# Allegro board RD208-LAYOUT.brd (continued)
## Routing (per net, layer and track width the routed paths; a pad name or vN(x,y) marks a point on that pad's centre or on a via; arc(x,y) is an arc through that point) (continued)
N16690281: length 1.4
  TOP w0.6: R284.1 189.1,115.05 D71.A
N16690501: length 1.4
  TOP w0.6: D72.A 189.1,124.3 R286.1
N16690719: length 1.4
  TOP w0.6: D73.A 189.1,133.55 R288.1
N16776249: length 3.3
  TOP w0.2: 163.5,104.18 R292.2 R291.1
N16781117: length 1.4
  TOP w0.3: IC2.15 153.12,32.62 R295.2
N16783087: length 1
  TOP w0.3: R27.1 R24.1
N16783507: length 2.2
  TOP w0.2: IC2.4 v1(161.8,33.92)
  BOTTOM w0.3: v1(161.8,33.92) 162.68,33.92 R297.1
N159286810: length 1.1
  TOP w0.5: C12.1 R14.2
N159479370: length 1.5
  BOTTOM w0.8: R29.1 R28.2

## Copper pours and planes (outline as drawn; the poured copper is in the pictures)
5V_IN on TOP: 78.55,129 78.42,129.03 78.33,129.12 78.3,129.25 78.3,130.35 78.27,130.47 78.23,130.52 77.07,131.68 77.03,131.73 77,131.85 77,143.9 77.04,144.01 77.15,144.05 79.15,144.05 79.26,144.01 79.3,143.9 79.3,136.2 79.29,136.14 79.23,136.03 79.02,135.82 78.96,135.71 78.95,135.65 78.95,133.7 78.98,133.58 79.02,133.53 79.28,133.27 79.32,133.22 79.35,133.1 79.35,130.85 79.34,130.79 79.28,130.68 79.27,130.67 79.21,130.56 79.2,130.5 79.2,129.25 79.17,129.12 79.08,129.03 78.95,129
5V_RTN on TOP: 80.55,129 80.42,129.03 80.33,129.12 80.3,129.25 80.3,130.5 80.27,130.62 80.18,130.73 80.15,130.85 80.15,133.1 80.16,133.16 80.22,133.27 80.48,133.53 80.54,133.64 80.55,133.7 80.55,135.65 80.52,135.77 80.48,135.82 80.27,136.03 80.23,136.08 80.2,136.2 80.2,143.9 80.24,144.01 80.35,144.05 82.35,144.05 82.46,144.01 82.5,143.9 82.5,131.85 82.49,131.79 82.43,131.68 81.27,130.52 81.21,130.41 81.2,130.35 81.2,129.25 81.17,129.12 81.08,129.03 80.95,129
GND on BOTTOM (solid shape): 222.03,10.28 222.5,10.6 222.97,10.28 223.52,8.85 223.24,8.2 222.59,8.49 222.58,8.53 222.42,8.53 222.41,8.49 221.76,8.2 221.48,8.85
GND on TOP: 164.5,88.45 164.44,88.46 164.33,88.52 163.57,89.28 163.53,89.33 163.5,89.45 163.5,96.1 163.47,96.22 163.43,96.27 163.24,96.46 163.21,96.5 163.2,96.56 163.2,97.5 163.23,97.62 163.32,97.72 163.45,97.75 165,97.75 165.22,97.84 165.31,98.05 165.31,98.75 165.35,98.86 165.46,98.9 170.93,98.9 170.98,98.89 171.03,98.86 171.26,98.63 171.29,98.58 171.3,98.53 171.3,88.6 171.26,88.49 171.15,88.45
GND on TOP: 156.3,35.75 156.18,35.78 156.08,35.88 156.05,36 156.05,36.7 156.02,36.83 155.93,36.92 155.8,36.95 153.6,36.95 153.47,36.98 153.38,37.08 153.35,37.2 153.35,40 153.38,40.12 153.47,40.22 153.6,40.25 161.9,40.25 162.03,40.22 162.12,40.12 162.15,40 162.15,37.2 162.12,37.08 162.03,36.98 161.9,36.95 159.2,36.95 159.07,36.92 158.98,36.83 158.95,36.7 158.95,36 158.92,35.88 158.82,35.78 158.7,35.75
GND on TOP: 98.95,20.25 98.83,20.28 98.73,20.38 98.7,20.5 98.7,25.6 98.73,25.73 98.83,25.82 98.95,25.85 100.45,25.85 100.58,25.82 100.67,25.73 100.7,25.6 100.7,20.5 100.67,20.38 100.58,20.28 100.45,20.25
GND on TOP: 45.95,13.93 45.83,13.96 45.73,14.05 45.7,14.18 45.7,15.19 45.73,15.27 45.79,15.32 45.88,15.38 45.95,15.47 46,15.54 46.08,15.56 47.35,15.56 47.48,15.59 47.57,15.69 47.6,15.81 47.6,16.75 47.63,16.88 47.73,16.97 47.85,17 49.1,17 49.23,16.97 49.32,16.88 49.35,16.75 49.35,15.81 49.38,15.69 49.48,15.59 49.6,15.56 49.69,15.56 49.75,15.55 49.86,15.49 50.18,15.17 50.22,15.12 50.25,15 50.25,14.18 50.22,14.05 50.12,13.96 50,13.93
GND on TOP: 56.2,11.35 56.09,11.39 56.05,11.5 56.05,13.95 56.08,14.07 56.17,14.17 56.3,14.2 57.7,14.2 57.91,14.29 58,14.5 58,15 57.91,15.21 57.7,15.3 56.3,15.3 56.17,15.33 56.08,15.43 56.05,15.55 56.05,16.62 55.96,16.84 55.75,16.93 53.6,16.93 53.55,16.94 53.5,16.97 52.38,18.04 52.23,18.07 52.1,18.07 51.99,18.12 51.95,18.23 51.95,18.83 52.02,19.01 52.19,19.08 52.22,19.08 52.53,19.13 52.77,19.34 52.83,19.39 52.92,19.4 52.98,19.4 55.45,19.4 55.56,19.36 55.6,19.25 55.6,18.15 55.69,17.94 55.9,17.85 57.5,17.85 57.71,17.94 57.8,18.15 57.8,19.15 57.84,19.26 57.95,19.3 58.5,19.3 58.61,19.26 58.65,19.15 58.65,11.6 58.62,11.47 58.52,11.38 58.4,11.35
GND on TOP: 48.2,20.2 48.08,20.23 47.98,20.32 47.95,20.45 47.95,22.9 47.96,22.96 48.02,23.07 48.33,23.38 48.38,23.42 48.5,23.45 50.8,23.45 50.87,23.42 50.9,23.35 50.9,22.1 50.87,22.03 50.8,22 50.33,22 50.11,21.91 50.02,21.7 50.02,21.5 50,21.43 49.92,21.4 49.6,21.4 49.48,21.37 49.38,21.27 49.35,21.15 49.35,20.45 49.32,20.32 49.23,20.23 49.1,20.2
GND on TOP: 43.94,63.5 44,63.49 44.04,63.46 47,60.5 57.2,60.5 57.32,60.53 57.37,60.57 57.53,60.73 57.58,60.77 57.7,60.8 58.25,60.8 58.38,60.77 58.47,60.67 58.5,60.55 58.5,45.4 58.42,44.53 58.2,43.69 57.83,42.9 57.33,42.19 56.71,41.57 56,41.07 55.21,40.7 54.37,40.48 53.5,40.4 35.7,40.4 34.83,40.48 33.99,40.7 33.2,41.07 32.49,41.57 31.87,42.19 31.37,42.9 31,43.69 30.78,44.53 30.7,45.4 30.7,52.75 30.67,52.87 30.63,52.92 28.37,55.18 28.33,55.23 28.3,55.35 28.3,62.44 28.31,62.5 28.34,62.54 29.26,63.46 29.3,63.49 29.36,63.5 ; 1 cut-out
GND on TOP: 42.25,11.1 42.36,11.06 42.4,10.95 42.4,9.1 42.49,8.89 42.7,8.8 45.6,8.8 45.81,8.89 45.9,9.1 45.9,10.3 45.94,10.41 46.05,10.45 50.33,10.45 50.4,10.44 50.51,10.38 51.29,9.6 51.42,9.51 51.57,9.48 68.53,9.48 68.58,9.47 68.62,9.45 68.71,9.39 68.74,9.36 68.76,9.33 69.28,8.71 70.05,8.48 70.7,8.48 70.83,8.45 70.92,8.36 70.95,8.23 70.95,1.15 70.91,1.04 70.8,1 10.35,1 10.24,1.04 10.2,1.15 10.2,5 8.68,8.68 5,10.2 1.15,10.2 1.04,10.24 1,10.35 1,24.25 1.03,24.38 1.12,24.47 1.25,24.5 11.95,24.5 12.01,24.49 12.12,24.43 20.38,16.17 20.49,16.11 20.55,16.1 42.6,16.1 42.73,16.07 42.82,15.97 42.83,15.94 42.84,15.9 42.84,14.4 42.8,14.28 42.71,14.18 42.59,14.15 39.35,14.15 39.23,14.12 39.13,14.03 39.1,13.9 39.1,12.5 39.16,12.33 39.37,12.16 39.4,12.08 39.4,11.65 39.56,11.26 39.95,11.1 ; 1 cut-out
GND on TOP: 219.75,139.65 219.71,139.54 219.6,139.5 197.15,139.5 197.04,139.54 197,139.65 197,142.7 187.2,142.7 187.08,142.67 187.03,142.63 186.82,142.42 186.77,142.38 186.65,142.35 185.75,142.35 185.62,142.38 185.53,142.47 185.5,142.6 185.5,148.75 185.53,148.88 185.62,148.97 185.75,149 209.99,149 210.01,149 219.6,149 219.71,148.96 219.75,148.85 ; 1 cut-out
GND on TOP: 57.95,142.5 57.83,142.53 57.73,142.62 57.7,142.75 57.7,145 57.66,145.51 57.56,146.02 57.51,146.17 57.46,146.32 57.45,146.36 57.45,148.75 57.48,148.88 57.58,148.97 57.7,149 61.75,149 61.82,148.97 61.85,148.9 61.85,147.78 61.82,147.7 61.75,147.68 61,147.68 60.79,147.59 60.7,147.38 60.7,146.62 60.79,146.41 61,146.32 61.75,146.32 61.82,146.3 61.85,146.22 61.85,145.28 61.82,145.2 61.75,145.18 61,145.18 60.79,145.09 60.7,144.88 60.7,144.12 60.79,143.91 61,143.82 61.75,143.82 61.82,143.8 61.85,143.72 61.85,142.75 61.82,142.62 61.73,142.53 61.6,142.5
GND on TOP: 154.05,29.95 153.93,29.98 153.83,30.07 153.8,30.2 153.8,31.4 153.84,31.51 153.95,31.55 155.8,31.55 155.93,31.58 156.02,31.68 156.05,31.8 156.05,32.55 156.08,32.67 156.18,32.77 156.3,32.8 158.7,32.8 158.82,32.77 158.92,32.67 158.95,32.55 158.95,31.8 158.98,31.68 159.07,31.58 159.2,31.55 161.15,31.55 161.35,31.63 161.45,31.82 161.5,31.92 161.62,31.95 161.65,31.95 162.85,31.95 162.97,31.92 163.07,31.82 163.1,31.7 163.1,30.2 163.07,30.07 162.97,29.98 162.85,29.95
GND on BOTTOM: 57.7,146.45 57.58,146.48 57.48,146.57 57.45,146.7 57.45,148.35 57.48,148.47 57.58,148.57 57.7,148.6 60.4,148.6 60.52,148.57 60.62,148.47 60.65,148.35 60.65,146.7 60.62,146.57 60.52,146.48 60.4,146.45
GND on BOTTOM: 219.75,139.65 219.71,139.54 219.6,139.5 197.15,139.5 197.04,139.54 197,139.65 197,142.35 185.75,142.35 185.62,142.38 185.53,142.47 185.5,142.6 185.5,148.75 185.53,148.88 185.62,148.97 185.75,149 209.99,149 210.01,149 219.6,149 219.71,148.96 219.75,148.85 ; 1 cut-out
GND on BOTTOM: 164.6,88.45 164.47,88.48 164.38,88.58 164.35,88.7 164.35,98.65 164.38,98.78 164.47,98.87 164.6,98.9 170.89,98.9 170.95,98.89 171.06,98.83 171.25,98.64 171.27,98.62 171.28,98.59 171.29,98.55 171.3,98.5 171.3,88.7 171.3,88.69 171.22,88.52 171.05,88.45
GND on BOTTOM: outline of 119 points within 1,1 68.15,27.1
GND on BOTTOM: 151.46,39.96 151.5,39.99 151.56,40 163.44,40 163.5,39.99 163.54,39.96 163.96,39.54 163.99,39.5 164,39.44 164,28.6 163.99,28.54 163.93,28.43 163.57,28.07 163.52,28.03 163.4,28 151.6,28 151.54,28.01 151.43,28.07 151.07,28.43 151.03,28.48 151,28.6 151,39.44 151.01,39.5 151.04,39.54 ; 1 cut-out
GND on BOTTOM: 196.15,3.45 196.08,3.48 196.05,3.55 196.05,5.7 196.08,5.77 196.15,5.8 197.55,5.8 197.62,5.77 197.65,5.7 197.65,3.55 197.62,3.48 197.55,3.45
GND on BOTTOM: 95.5,18.5 95.44,18.51 95.33,18.57 94.62,19.28 94.58,19.33 94.55,19.45 94.55,25.4 94.56,25.46 94.62,25.57 94.98,25.93 95.03,25.97 95.15,26 114.2,26 114.26,25.99 114.37,25.93 115.78,24.52 115.82,24.47 115.85,24.35 115.85,18.75 115.82,18.62 115.72,18.53 115.6,18.5
GND on CONDUCTIVE2: outline of 142 points within 1,15.5 239,149 ; 7 cut-outs
GND on CONDUCTIVE3: 220.07,140.16 219.86,139.84 219.52,139.62 219.15,139.55 198,139.55 197.61,139.63 197.29,139.84 197.07,140.18 197,140.55 197,141.35 196.93,141.72 196.71,142.06 196.39,142.27 196,142.35 185.75,142.35 185.62,142.38 185.53,142.47 185.5,142.6 185.5,148.75 185.53,148.88 185.62,148.97 185.75,149 209.99,149 210.01,149 220,149 220.11,148.96 220.15,148.85 220.15,140.55 ; 1 cut-out
GND on CONDUCTIVE4: 52.85,136.9 52.73,136.93 52.63,137.03 52.6,137.15 52.6,141.05 52.63,141.18 52.73,141.27 52.85,141.3 53.99,141.3 57.28,143.3 57.02,147.14 57,147.17 57,147.2 57,148.9 57.03,148.97 57.1,149 61.1,149 61.17,148.97 61.2,148.9 61.2,144.5 61.19,144.44 61.13,144.33 58.02,141.22 57.96,141.11 57.95,141.05 57.95,139.55 57.94,139.48 57.88,139.37 55.65,137.15 55.59,137.07 55.56,136.98 55.52,136.92 55.46,136.9
GND on CONDUCTIVE4: 219.6,139.65 219.56,139.54 219.45,139.5 197.06,139.5 197,139.51 196.96,139.54 194.15,142.35 185.75,142.35 185.62,142.38 185.53,142.47 185.5,142.6 185.5,148.75 185.53,148.88 185.62,148.97 185.75,149 209.99,149 210.01,149 219.45,149 219.56,148.96 219.6,148.85 ; 1 cut-out
GND on CONDUCTIVE4: outline of 103 points within 1,1 229.8,39.4 ; 1 cut-out
GND on CONDUCTIVE5: 219.75,139.65 219.71,139.54 219.6,139.5 197.16,139.5 197.1,139.51 197.06,139.54 194.25,142.35 185.75,142.35 185.62,142.38 185.53,142.47 185.5,142.6 185.5,148.75 185.53,148.88 185.62,148.97 185.75,149 209.99,149 210.01,149 219.6,149 219.71,148.96 219.75,148.85 ; 1 cut-out
GND_D on TOP: outline of 96 points within 158.3,121.6 169.16,130.3
GND_D on TOP: outline of 118 points within 152.45,121.6 161.28,130.3
GND_D on TOP: 153.9,131.1 153.83,131.13 153.8,131.2 153.79,131.27 153.75,131.37 153.75,131.39 153.75,133.25 153.66,133.46 153.45,133.55 151.95,133.55 151.88,133.58 151.85,133.65 151.85,134.25 151.76,134.46 151.55,134.55 150.8,134.55 150.73,134.58 150.7,134.65 150.7,134.9 150.67,135.03 150.6,135.15 147.06,138.68 147.04,138.71 147.03,138.75 147.03,141 147.06,141.07 147.13,141.1 148.05,141.1 148.15,141.08 148.23,141.03 154.47,134.78 154.49,134.75 154.5,134.71 154.5,134.61 154.49,134.57 154.38,134.43 154.35,134.3 154.35,132.75 154.44,132.54 154.65,132.45 156.15,132.45 156.22,132.42 156.25,132.35 156.25,132.04 156.24,132 156.22,131.97 155.38,131.13 155.35,131.11 155.31,131.1
GND_D on TOP: 160.95,133.55 160.88,133.58 160.85,133.65 160.85,134.25 160.76,134.46 160.55,134.55 159.74,134.55 159.7,134.56 159.67,134.58 154.48,139.77 154.46,139.8 154.45,139.84 154.45,140.25 154.46,140.3 154.51,140.34 154.56,140.35 155.71,140.35 155.75,140.35 155.78,140.33 161.65,134.45 161.77,134.38 161.9,134.35 163.51,134.35 163.55,134.34 163.58,134.32 163.97,133.93 163.99,133.9 164,133.86 164,133.65 163.97,133.58 163.9,133.55
GND_D on TOP: outline of 219 points within 71.55,103.7 171.83,115.85 ; 4 cut-outs
GND_D on TOP: 169.72,126.87 169.67,126.87 169.55,126.91 169.52,126.93 169.5,126.95 168.78,127.62 168.65,127.65 165.15,127.65 165.04,127.69 165,127.8 165,128.25 164.91,128.46 164.7,128.55 164.25,128.55 164.14,128.59 164.1,128.7 164.1,129.5 164.01,129.71 163.8,129.8 163,129.8 162.97,129.8 162.85,129.84 162.8,129.95 162.8,130.05 162.85,130.16 162.97,130.2 163,130.2 163.8,130.2 163.9,130.22 164.03,130.29 164.08,130.3 164.75,130.3 164.86,130.26 164.9,130.15 164.9,129.2 164.99,128.99 165.2,128.9 166.19,128.9 166.25,128.89 166.3,128.86 166.87,128.33 167,128.3 169.69,128.3 169.75,128.29 169.8,128.26 169.91,128.15 169.94,128.1 169.95,128.04 169.95,127.02 169.91,126.91 169.8,126.87
GND_D on TOP: outline of 85 points within 118.75,126.9 126.75,132.6
GND_D on TOP: 148.56,119.85 148.5,119.86 148.45,119.89 147.19,121.15 147.16,121.2 147.15,121.26 147.15,123.45 147.19,123.56 147.3,123.6 148.25,123.6 148.36,123.56 148.4,123.45 148.4,121.75 148.43,121.62 148.5,121.5 148.76,121.25 148.79,121.2 148.8,121.14 148.8,120 148.76,119.89 148.65,119.85
GND_D on TOP: 120.06,113 120,113.01 119.95,113.04 116.88,116.07 116.75,116.1 115.7,116.1 115.59,116.14 115.55,116.25 115.55,117.6 115.59,117.71 115.7,117.75 116.84,117.75 116.9,117.74 116.95,117.71 120.52,114.18 120.65,114.15 124.63,114.15 124.7,114.13 124.86,113.99 125,113.95 127.75,113.95 127.82,113.93 127.98,113.79 128.12,113.75 129.1,113.75 129.21,113.71 129.34,113.39 129.55,113.3 129.7,113.15 129.55,113
GND_D on TOP: outline of 1189 points within 62.65,61 179.55,149 ; 19 cut-outs
GND_D on BOTTOM: outline of 1034 points within 72.15,101.23 179.55,149 ; 45 cut-outs
GND_D on BOTTOM: 69.6,129.05 69.53,129.08 69.5,129.15 69.5,130.95 69.41,131.16 69.2,131.25 67.8,131.25 67.59,131.16 67.5,130.95 67.5,130.45 67.5,130.41 67.48,130.33 67.4,130.3 66.32,130.3 66.25,130.32 66.2,130.32 64.55,130.32 64.48,130.35 64.45,130.42 64.45,135.83 64.48,135.9 64.55,135.93 66.2,135.93 66.25,135.93 66.32,135.95 66.85,135.95 66.92,135.92 66.95,135.85 66.95,135.4 66.96,135.32 67,135.23 67,135.21 67,134.4 67.09,134.19 67.3,134.1 68.7,134.1 68.85,134.14 69,134.29 69.05,134.3 69.45,134.3 69.58,134.33 69.7,134.4 70.5,135.2 70.57,135.32 70.6,135.45 70.6,135.6 70.63,135.67 70.7,135.7 71.35,135.7 71.42,135.67 71.45,135.6 71.45,129.15 71.42,129.08 71.35,129.05
GND_D on BOTTOM: 69.6,119.8 69.53,119.83 69.5,119.9 69.5,121.7 69.41,121.91 69.2,122 67.8,122 67.59,121.91 67.5,121.7 67.5,121.2 67.5,121.16 67.48,121.08 67.4,121.05 66.32,121.05 66.25,121.07 66.2,121.07 64.55,121.07 64.48,121.1 64.45,121.17 64.45,126.58 64.48,126.65 64.55,126.68 66.2,126.68 66.25,126.68 66.32,126.7 66.85,126.7 66.92,126.67 66.95,126.6 66.95,126.15 66.96,126.07 67,125.98 67,125.96 67,125.15 67.09,124.94 67.3,124.85 68.7,124.85 68.85,124.89 69,125.04 69.05,125.05 69.45,125.05 69.58,125.08 69.7,125.15 70.5,125.95 70.57,126.07 70.6,126.2 70.6,126.35 70.63,126.42 70.7,126.45 71.35,126.45 71.42,126.42 71.45,126.35 71.45,119.9 71.42,119.83 71.35,119.8
GND_D on BOTTOM: 141.55,131.3 141.48,131.33 141.45,131.4 141.45,133.1 141.48,133.17 141.55,133.2 142.35,133.2 142.74,133.36 142.9,133.75 142.9,135.66 142.91,135.7 142.93,135.73 143.6,136.4 143.67,136.52 143.7,136.65 143.7,138.51 143.71,138.55 143.73,138.58 146.22,141.07 146.25,141.09 146.29,141.1 153.67,141.1 153.75,141.06 153.76,140.98 154.3,140.3 154.84,140.98 154.85,141.06 154.93,141.1 156.06,141.1 156.1,141.09 156.13,141.07 156.21,141 156.22,140.98 156.23,140.96 156.33,140.68 156.53,140.4 156.85,140.3 164.7,140.3 164.77,140.27 164.8,140.2 164.8,139.59 164.79,139.55 164.77,139.52 164.03,138.78 164,138.76 163.96,138.75 150.85,138.75 150.72,138.72 150.6,138.65 143.28,131.33 143.25,131.31 143.21,131.3 142.35,131.3 142.28,131.3
GND_D on BOTTOM: 69.6,138.3 69.53,138.33 69.5,138.4 69.5,140.2 69.41,140.41 69.2,140.5 67.8,140.5 67.59,140.41 67.5,140.2 67.5,139.7 67.5,139.66 67.48,139.58 67.4,139.55 66.32,139.55 66.25,139.57 66.2,139.57 64.55,139.57 64.48,139.6 64.45,139.67 64.45,145.05 64.38,145.13 64.35,145.15 63.82,145.68 63.78,145.73 63.75,145.85 63.75,147.96 63.76,148 63.78,148.03 64.23,148.48 64.28,148.52 64.4,148.55 70.6,148.55 70.67,148.52 70.7,148.45 70.7,147.5 70.8,147.18 71.08,146.98 71.36,146.88 71.38,146.87 71.42,146.83 71.44,146.8 71.45,146.76 71.45,138.4 71.42,138.33 71.35,138.3
GND_D on BOTTOM: outline of 109 points within 64.45,102.1 75.95,117.45
GND_D on BOTTOM: 64.55,58.2 64.48,58.23 64.45,58.3 64.45,67.48 64.48,67.55 64.55,67.58 66.7,67.58 66.77,67.55 66.8,67.48 66.8,67 66.81,66.92 66.85,66.83 66.85,66.81 66.85,66 66.94,65.79 67.15,65.7 68.45,65.7 68.52,65.67 68.55,65.6 68.55,65.34 68.54,65.3 68.52,65.27 67.78,64.53 67.75,64.51 67.71,64.5 66.4,64.5 66.01,64.34 65.85,63.95 65.85,62.03 65.84,62 66.37,61.24 66.84,62.03 66.71,62.3 66.7,62.32 66.7,62.34 66.7,62.41 66.71,62.45 66.73,62.48 68.44,64.2 68.48,64.22 68.51,64.23 68.95,64.23 69.02,64.2 69.05,64.13 69.05,59.3 69.02,59.23 68.95,59.2 68.25,59.2 67.86,59.04 67.7,58.65 67.7,58.3 67.67,58.23 67.6,58.2
GND_D on CONDUCTIVE2: 72.3,127.25 72.8,126.05 74,125.55 85.5,125.55 86.7,126.05 87.2,127.25 87.2,148.85 87.24,148.96 87.35,149 114.65,149 114.76,148.96 114.8,148.85 114.8,145 120,139.8 125.2,145 125.2,148.85 125.24,148.96 125.35,149 179.4,149 179.51,148.96 179.55,148.85 179.55,63.85 179.51,63.74 179.4,63.7 175.85,63.7 175.74,63.74 175.7,63.85 175.7,99.5 175.53,100.34 175.06,101.06 173.06,103.06 172.34,103.53 171.5,103.7 71.25,103.7 69.69,103.06 69.05,101.5 69.05,58.35 69.01,58.24 68.9,58.2 64.6,58.2 64.49,58.24 64.45,58.35 64.45,144.93 64.41,145.08 64.36,145.14 63.84,145.66 63.79,145.72 63.75,145.87 63.75,148.7 63.79,148.85 63.9,148.96 64.05,149 72.15,149 72.26,148.96 72.3,148.85 ; 4 cut-outs
GND_D on CONDUCTIVE3: outline of 488 points within 63.75,63.7 179.55,149 ; 3 cut-outs
GND_D on CONDUCTIVE3: 64.6,58.2 64.49,58.24 64.45,58.35 64.45,70.75 64.49,70.86 64.6,70.9 66.1,70.9 66.79,71.36 66.63,72.18 65.79,73.02 65.76,73.07 65.75,73.12 65.75,80 65.79,80.11 65.9,80.15 66.1,80.15 66.85,80.9 66.1,81.65 65.9,81.65 65.79,81.69 65.75,81.8 65.75,89.25 65.79,89.36 65.9,89.4 66.1,89.4 66.85,90.15 66.1,90.9 65.9,90.9 65.79,90.94 65.75,91.05 65.75,98.5 65.79,98.61 65.9,98.65 66.1,98.65 66.85,99.4 66.1,100.15 65.9,100.15 65.79,100.19 65.75,100.3 65.75,107.03 65.76,107.08 65.79,107.13 69.12,110.46 69.17,110.49 69.22,110.5 81.53,110.5 81.58,110.49 81.63,110.46 84.47,107.62 85.37,106.72 85.61,106.56 85.9,106.5 113.28,106.5 113.33,106.49 113.38,106.46 115.3,104.54 115.33,104.49 115.34,104.43 115.34,103.85 115.3,103.74 115.19,103.7 71.25,103.7 69.69,103.06 69.05,101.5 69.05,58.35 69.01,58.24 68.9,58.2
GND_D on CONDUCTIVE4: outline of 524 points within 63.55,58.2 179.55,149 ; 4 cut-outs
GND_D on CONDUCTIVE5: 72.3,127.25 72.8,126.05 74,125.55 85.5,125.55 86.7,126.05 87.2,127.25 87.2,148.85 87.24,148.96 87.35,149 114.65,149 114.76,148.96 114.8,148.85 114.8,145 120,139.8 125.2,145 125.2,148.85 125.24,148.96 125.35,149 179.4,149 179.51,148.96 179.55,148.85 179.55,63.85 179.51,63.74 179.4,63.7 175.85,63.7 175.74,63.74 175.7,63.85 175.7,99.5 175.53,100.34 175.06,101.06 173.06,103.06 172.34,103.53 171.5,103.7 71.25,103.7 69.69,103.06 69.05,101.5 69.05,58.35 69.01,58.24 68.9,58.2 64.6,58.2 64.49,58.24 64.45,58.35 64.45,144.93 64.41,145.08 64.36,145.14 63.84,145.66 63.79,145.72 63.75,145.87 63.75,148.7 63.79,148.85 63.9,148.96 64.05,149 72.15,149 72.26,148.96 72.3,148.85 ; 5 cut-outs
HVU_1_4 on TOP: 30.85,109.15 30.73,109.18 30.63,109.28 30.6,109.4 30.6,118.3 30.63,118.42 30.73,118.52 30.85,118.55 36,118.55 36.12,118.52 36.22,118.42 36.25,118.3 36.25,112.6 36.28,112.47 36.38,112.38 36.5,112.35 37.1,112.35 37.23,112.32 37.32,112.22 37.35,112.1 37.35,109.4 37.32,109.28 37.23,109.18 37.1,109.15
HVU_1_4 on TOP: 30.95,65.05 30.82,65.08 30.73,65.17 30.7,65.3 30.7,74 30.73,74.12 30.82,74.22 30.95,74.25 36.2,74.25 36.33,74.22 36.42,74.12 36.45,74 36.45,73.3 36.52,73.12 36.7,73.05 40.85,73.05 40.96,73.01 41,72.9 41,66.4 40.96,66.29 40.85,66.25 36.7,66.25 36.52,66.18 36.45,66 36.45,65.3 36.42,65.17 36.33,65.08 36.2,65.05
HVU_1_4 on BOTTOM: 30.95,65.05 30.82,65.08 30.73,65.17 30.7,65.3 30.7,74 30.73,74.12 30.82,74.22 30.95,74.25 36.05,74.25 36.17,74.22 36.27,74.12 36.3,74 36.3,65.3 36.27,65.17 36.17,65.08 36.05,65.05
HVU_1_4 on BOTTOM: 30.85,109.15 30.73,109.18 30.63,109.28 30.6,109.4 30.6,118.3 30.63,118.42 30.73,118.52 30.85,118.55 35.95,118.55 36.08,118.52 36.17,118.42 36.2,118.3 36.2,109.4 36.17,109.28 36.08,109.18 35.95,109.15
HVU_1_4 on CONDUCTIVE3: outline of 86 points within 1,65 36.4,118.55
HVU_2_4 on TOP: 30.95,75.8 30.82,75.83 30.73,75.92 30.7,76.05 30.7,84.75 30.73,84.88 30.82,84.97 30.95,85 36.2,85 36.33,84.97 36.42,84.88 36.45,84.75 36.45,84.05 36.52,83.87 36.7,83.8 40.85,83.8 40.96,83.76 41,83.65 41,77.15 40.96,77.04 40.85,77 36.7,77 36.52,76.93 36.45,76.75 36.45,76.05 36.42,75.92 36.33,75.83 36.2,75.8
HVU_2_4 on TOP: 30.85,119.9 30.73,119.93 30.63,120.03 30.6,120.15 30.6,129 30.63,129.12 30.73,129.22 30.85,129.25 36,129.25 36.12,129.22 36.22,129.12 36.25,129 36.25,123.35 36.28,123.22 36.38,123.13 36.5,123.1 37.1,123.1 37.23,123.07 37.32,122.97 37.35,122.85 37.35,120.15 37.32,120.03 37.23,119.93 37.1,119.9
HVU_2_4 on BOTTOM: 30.95,75.8 30.82,75.83 30.73,75.92 30.7,76.05 30.7,84.75 30.73,84.88 30.82,84.97 30.95,85 36.05,85 36.17,84.97 36.27,84.88 36.3,84.75 36.3,76.05 36.27,75.92 36.17,75.83 36.05,75.8
HVU_2_4 on BOTTOM: 30.85,119.9 30.73,119.93 30.63,120.03 30.6,120.15 30.6,129 30.63,129.12 30.73,129.22 30.85,129.25 35.95,129.25 36.08,129.22 36.17,129.12 36.2,129 36.2,120.15 36.17,120.03 36.08,119.93 35.95,119.9
HVU_2_4 on CONDUCTIVE2: 23.4,75.75 22.53,75.83 21.69,76.05 20.9,76.42 20.19,76.92 19.57,77.54 19.07,78.25 18.7,79.04 18.48,79.88 18.4,80.75 18.4,105 18.33,105.37 18.11,105.71 17.79,105.92 17.4,106 11,106 10.63,105.93 10.29,105.71 10.08,105.39 10,105 10,101 9.92,100.61 9.71,100.29 9.37,100.07 9,100 2,100 1.61,100.08 1.29,100.29 1.07,100.63 1,101 1,110.5 1.08,111.37 1.3,112.21 1.67,113 2.17,113.71 2.79,114.33 3.5,114.83 4.29,115.2 5.13,115.42 6,115.5 9.5,115.5 9.87,115.57 10.21,115.79 10.42,116.11 10.5,116.5 10.5,124.25 10.58,125.12 10.8,125.96 11.17,126.75 11.67,127.46 12.29,128.08 13,128.58 13.79,128.95 14.63,129.17 15.5,129.25 36.25,129.25 36.36,129.21 36.4,129.1 36.4,120.1 36.36,119.99 36.25,119.95 29.4,119.95 29.03,119.88 28.69,119.66 28.48,119.34 28.4,118.95 28.4,86.05 28.47,85.68 28.69,85.34 29.01,85.13 29.4,85.05 36.25,85.05 36.36,85.01 36.4,84.9 36.4,75.9 36.36,75.79 36.25,75.75
HVU_3_4 on TOP: 28.45,130.65 28.32,130.68 28.23,130.78 28.2,130.9 28.2,137.5 28.23,137.62 28.32,137.72 28.45,137.75 36,137.75 36.12,137.72 36.22,137.62 36.25,137.5 36.25,134.1 36.28,133.97 36.38,133.88 36.5,133.85 37.1,133.85 37.23,133.82 37.32,133.72 37.35,133.6 37.35,130.9 37.32,130.78 37.23,130.68 37.1,130.65
HVU_3_4 on TOP: 30.95,86.55 30.82,86.58 30.73,86.67 30.7,86.8 30.7,95.5 30.73,95.62 30.82,95.72 30.95,95.75 36.2,95.75 36.33,95.72 36.42,95.62 36.45,95.5 36.45,94.8 36.52,94.62 36.7,94.55 40.85,94.55 40.96,94.51 41,94.4 41,87.9 40.96,87.79 40.85,87.75 36.7,87.75 36.52,87.68 36.45,87.5 36.45,86.8 36.42,86.67 36.33,86.58 36.2,86.55
HVU_3_4 on BOTTOM: 30.95,86.55 30.82,86.58 30.73,86.67 30.7,86.8 30.7,95.5 30.73,95.62 30.82,95.72 30.95,95.75 36.05,95.75 36.17,95.72 36.27,95.62 36.3,95.5 36.3,86.8 36.27,86.67 36.17,86.58 36.05,86.55
HVU_3_4 on BOTTOM: 28.4,130.65 28.27,130.68 28.18,130.78 28.15,130.9 28.15,137.5 28.18,137.62 28.27,137.72 28.4,137.75 36,137.75 36.12,137.72 36.22,137.62 36.25,137.5 36.25,130.9 36.22,130.78 36.12,130.68 36,130.65
HVU_3_4 on CONDUCTIVE4: outline of 81 points within 1,86.3 37.9,139.9
HVV_1_4 on TOP: 105.8,69.85 105.67,69.88 105.58,69.97 105.55,70.1 105.55,75.25 105.58,75.38 105.67,75.47 105.8,75.5 111.4,75.5 111.53,75.53 111.62,75.62 111.65,75.75 111.65,76.35 111.68,76.47 111.78,76.57 111.9,76.6 114.6,76.6 114.72,76.57 114.82,76.47 114.85,76.35 114.85,70.1 114.82,69.97 114.72,69.88 114.6,69.85
HVV_1_4 on TOP: 151.25,67.55 151.19,67.56 151.08,67.62 149.82,68.88 149.78,68.93 149.75,69.05 149.75,75.45 149.78,75.58 149.88,75.67 150,75.7 150.7,75.7 150.88,75.77 150.95,75.95 150.95,80.1 150.99,80.21 151.1,80.25 157.6,80.25 157.71,80.21 157.75,80.1 157.75,75.95 157.82,75.77 158,75.7 158.7,75.7 158.82,75.67 158.92,75.58 158.95,75.45 158.95,68.85 158.94,68.79 158.88,68.68 157.82,67.62 157.77,67.58 157.65,67.55
HVV_1_4 on BOTTOM: 151.35,67.5 151.29,67.51 151.18,67.57 149.82,68.93 149.78,68.98 149.75,69.1 149.75,75.3 149.78,75.42 149.88,75.52 150,75.55 156.3,75.55 156.43,75.52 156.52,75.42 156.55,75.3 156.55,69.1 156.54,69.04 156.48,68.93 155.12,67.57 155.07,67.53 154.95,67.5
HVV_1_4 on BOTTOM: 105.8,69.85 105.67,69.88 105.58,69.97 105.55,70.1 105.55,75.2 105.58,75.33 105.67,75.42 105.8,75.45 114.6,75.45 114.72,75.42 114.82,75.33 114.85,75.2 114.85,70.1 114.82,69.97 114.72,69.88 114.6,69.85
HVV_1_4 on CONDUCTIVE3: 138.75,52.75 138.36,52.83 138.04,53.04 137.82,53.38 137.75,53.75 137.75,56 137.68,56.37 137.46,56.71 137.14,56.92 136.75,57 110.45,57 109.58,57.08 108.74,57.3 107.95,57.67 107.24,58.17 106.62,58.79 106.12,59.5 105.75,60.29 105.53,61.13 105.45,62 105.45,75.85 105.49,75.96 105.6,76 114.7,76 114.81,75.96 114.85,75.85 114.85,68 114.92,67.63 115.14,67.29 115.46,67.08 115.85,67 148.7,67 149.07,67.07 149.41,67.29 149.62,67.61 149.7,68 149.7,75.5 149.74,75.61 149.85,75.65 158.85,75.65 158.96,75.61 159,75.5 159,63.81 158.92,63.42 158.71,63.11 153.54,57.94 153.21,57.72 152.84,57.65 148.06,57.65 147.69,57.58 147.36,57.36 142.79,52.79 142.75,52.76 142.69,52.75
HVV_2_4 on TOP: 95.05,69.85 94.92,69.88 94.83,69.97 94.8,70.1 94.8,75.25 94.83,75.38 94.92,75.47 95.05,75.5 100.65,75.5 100.78,75.53 100.87,75.62 100.9,75.75 100.9,76.35 100.93,76.47 101.03,76.57 101.15,76.6 103.85,76.6 103.97,76.57 104.07,76.47 104.1,76.35 104.1,70.1 104.07,69.97 103.97,69.88 103.85,69.85
HVV_2_4 on TOP: 139.25,69.95 139.12,69.98 139.03,70.08 139,70.2 139,75.45 139.03,75.58 139.12,75.67 139.25,75.7 139.95,75.7 140.13,75.77 140.2,75.95 140.2,80.1 140.24,80.21 140.35,80.25 146.85,80.25 146.96,80.21 147,80.1 147,75.95 147.07,75.77 147.25,75.7 147.95,75.7 148.07,75.67 148.17,75.58 148.2,75.45 148.2,70.2 148.17,70.08 148.07,69.98 147.95,69.95
HVV_2_4 on BOTTOM: 139.25,69.95 139.12,69.98 139.03,70.08 139,70.2 139,75.3 139.03,75.42 139.12,75.52 139.25,75.55 147.95,75.55 148.07,75.52 148.17,75.42 148.2,75.3 148.2,70.2 148.17,70.08 148.07,69.98 147.95,69.95
HVV_2_4 on BOTTOM: 95.05,69.85 94.92,69.88 94.83,69.97 94.8,70.1 94.8,75.2 94.83,75.33 94.92,75.42 95.05,75.45 103.85,75.45 103.97,75.42 104.07,75.33 104.1,75.2 104.1,70.1 104.07,69.97 103.97,69.88 103.85,69.85
HVV_2_4 on CONDUCTIVE2: 107,52.5 106.61,52.58 106.29,52.79 106.07,53.13 106,53.5 106,56.65 105.93,57.02 105.71,57.36 105.39,57.57 105,57.65 99.75,57.65 98.88,57.73 98.04,57.95 97.25,58.32 96.54,58.82 95.92,59.44 95.42,60.15 95.05,60.94 94.83,61.78 94.75,62.65 94.75,75.35 94.79,75.5 94.9,75.61 95.05,75.65 103.95,75.65 104.06,75.61 104.1,75.5 104.1,68.65 104.17,68.28 104.39,67.94 104.71,67.73 105.1,67.65 137.95,67.65 138.32,67.72 138.66,67.94 138.87,68.26 138.95,68.65 138.95,75.5 138.99,75.61 139.1,75.65 148.1,75.65 148.21,75.61 148.25,75.5 148.25,62.65 148.17,61.78 147.95,60.94 147.58,60.15 147.08,59.44 146.46,58.82 145.75,58.32 144.96,57.95 144.12,57.73 143.25,57.65 138.5,57.65 138.13,57.58 137.79,57.36 137.58,57.04 137.5,56.65 137.5,53.5 137.42,53.11 137.21,52.79 136.87,52.57 136.5,52.5
HVV_3_4 on TOP: 128.5,69.95 128.38,69.98 128.28,70.08 128.25,70.2 128.25,75.45 128.28,75.58 128.38,75.67 128.5,75.7 129.2,75.7 129.38,75.77 129.45,75.95 129.45,80.1 129.49,80.21 129.6,80.25 136.1,80.25 136.21,80.21 136.25,80.1 136.25,75.95 136.32,75.77 136.5,75.7 137.2,75.7 137.32,75.67 137.42,75.58 137.45,75.45 137.45,70.2 137.42,70.08 137.32,69.98 137.2,69.95
HVV_3_4 on TOP: 85.4,68.65 85.28,68.68 85.18,68.78 85.15,68.9 85.15,75.25 85.18,75.38 85.28,75.47 85.4,75.5 89.9,75.5 90.03,75.53 90.12,75.62 90.15,75.75 90.15,76.35 90.18,76.47 90.28,76.57 90.4,76.6 93.1,76.6 93.22,76.57 93.32,76.47 93.35,76.35 93.35,68.9 93.32,68.78 93.22,68.68 93.1,68.65
HVV_3_4 on BOTTOM: 128.5,69.95 128.38,69.98 128.28,70.08 128.25,70.2 128.25,75.3 128.28,75.42 128.38,75.52 128.5,75.55 137.2,75.55 137.32,75.52 137.42,75.42 137.45,75.3 137.45,70.2 137.42,70.08 137.32,69.98 137.2,69.95
HVV_3_4 on BOTTOM: 85.4,68.65 85.28,68.68 85.18,68.78 85.15,68.9 85.15,75.2 85.18,75.33 85.28,75.42 85.4,75.45 93.1,75.45 93.22,75.42 93.32,75.33 93.35,75.2 93.35,68.9 93.32,68.78 93.22,68.68 93.1,68.65
HVV_3_4 on CONDUCTIVE4: 89.75,51.25 89.36,51.33 89.04,51.54 88.82,51.88 88.75,52.25 88.75,55.45 88.72,55.57 88.68,55.62 84.34,59.96 84.12,60.29 84.05,60.66 84.05,75.5 84.09,75.61 84.2,75.65 93.2,75.65 93.31,75.61 93.35,75.5 93.35,68 93.42,67.63 93.64,67.29 93.96,67.08 94.35,67 127.2,67 127.57,67.07 127.91,67.29 128.12,67.61 128.2,68 128.2,75.5 128.24,75.61 128.35,75.65 137.35,75.65 137.46,75.61 137.5,75.5 137.5,62 137.42,61.13 137.2,60.29 136.83,59.5 136.33,58.79 135.71,58.17 135,57.67 134.21,57.3 133.37,57.08 132.5,57 106.75,57 106.38,56.93 106.04,56.71 105.83,56.39 105.75,56 105.75,52.25 105.67,51.86 105.46,51.54 105.12,51.32 104.75,51.25
HVW_1_4 on TOP: 208,84.65 207.88,84.68 207.78,84.78 207.75,84.9 207.75,90.55 207.72,90.67 207.62,90.77 207.5,90.8 206.9,90.8 206.78,90.83 206.68,90.92 206.65,91.05 206.65,93.75 206.68,93.88 206.78,93.97 206.9,94 213.15,94 213.28,93.97 213.37,93.88 213.4,93.75 213.4,84.9 213.37,84.78 213.28,84.68 213.15,84.65
HVW_1_4 on TOP: 207.8,128.9 207.68,128.93 207.58,129.03 207.55,129.15 207.55,129.85 207.48,130.03 207.3,130.1 203.15,130.1 203.04,130.14 203,130.25 203,136.75 203.04,136.86 203.15,136.9 207.3,136.9 207.48,136.97 207.55,137.15 207.55,137.85 207.58,137.97 207.68,138.07 207.8,138.1 213.05,138.1 213.18,138.07 213.27,137.97 213.3,137.85 213.3,129.15 213.27,129.03 213.18,128.93 213.05,128.9
HVW_1_4 on BOTTOM: 208.05,84.65 207.93,84.68 207.83,84.78 207.8,84.9 207.8,93.75 207.83,93.88 207.93,93.97 208.05,94 213.15,94 213.28,93.97 213.37,93.88 213.4,93.75 213.4,84.9 213.37,84.78 213.28,84.68 213.15,84.65
HVW_1_4 on BOTTOM: 207.95,128.9 207.82,128.93 207.73,129.03 207.7,129.15 207.7,137.85 207.73,137.97 207.82,138.07 207.95,138.1 213.05,138.1 213.18,138.07 213.27,137.97 213.3,137.85 213.3,129.15 213.27,129.03 213.18,128.93 213.05,128.9
HVW_1_4 on CONDUCTIVE3: 207.9,84.65 207.75,84.69 207.64,84.8 207.6,84.95 207.6,93.85 207.64,93.96 207.75,94 215.25,94 215.62,94.07 215.96,94.29 216.17,94.61 216.25,95 216.25,127.85 216.18,128.22 215.96,128.56 215.64,128.77 215.25,128.85 207.85,128.85 207.72,128.88 207.63,128.97 207.6,129.1 207.6,137.9 207.63,138.03 207.72,138.12 207.85,138.15 221.25,138.15 222.12,138.07 222.96,137.85 223.75,137.48 224.46,136.98 225.08,136.36 225.58,135.65 225.95,134.86 226.17,134.02 226.25,133.15 226.25,128 226.32,127.63 226.54,127.29 226.86,127.08 227.25,127 231.5,127 231.89,126.92 232.21,126.71 232.43,126.37 232.5,126 232.5,106 232.42,105.61 232.21,105.29 231.87,105.07 231.5,105 227.25,105 226.88,104.93 226.54,104.71 226.33,104.39 226.25,104 226.25,89.65 226.17,88.78 225.95,87.94 225.58,87.15 225.08,86.44 224.46,85.82 223.75,85.32 222.96,84.95 222.12,84.73 221.25,84.65
HVW_2_4 on TOP: 207.8,118.15 207.68,118.18 207.58,118.28 207.55,118.4 207.55,119.1 207.48,119.28 207.3,119.35 203.15,119.35 203.04,119.39 203,119.5 203,126 203.04,126.11 203.15,126.15 207.3,126.15 207.48,126.22 207.55,126.4 207.55,127.1 207.58,127.22 207.68,127.32 207.8,127.35 213.05,127.35 213.18,127.32 213.27,127.22 213.3,127.1 213.3,118.4 213.27,118.28 213.18,118.18 213.05,118.15
HVW_2_4 on TOP: 208,73.9 207.88,73.93 207.78,74.03 207.75,74.15 207.75,79.8 207.72,79.92 207.62,80.02 207.5,80.05 206.9,80.05 206.78,80.08 206.68,80.17 206.65,80.3 206.65,83 206.68,83.12 206.78,83.22 206.9,83.25 213.15,83.25 213.28,83.22 213.37,83.12 213.4,83 213.4,74.15 213.37,74.03 213.28,73.93 213.15,73.9
HVW_2_4 on BOTTOM: 207.95,118.15 207.82,118.18 207.73,118.28 207.7,118.4 207.7,127.1 207.73,127.22 207.82,127.32 207.95,127.35 213.05,127.35 213.18,127.32 213.27,127.22 213.3,127.1 213.3,118.4 213.27,118.28 213.18,118.18 213.05,118.15
HVW_2_4 on BOTTOM: 208.05,73.95 207.93,73.98 207.83,74.08 207.8,74.2 207.8,83 207.83,83.12 207.93,83.22 208.05,83.25 213.15,83.25 213.28,83.22 213.37,83.12 213.4,83 213.4,74.2 213.37,74.08 213.28,73.98 213.15,73.95
HVW_2_4 on CONDUCTIVE2: 207.9,73.9 207.75,73.94 207.64,74.05 207.6,74.2 207.6,83.1 207.64,83.21 207.75,83.25 214.6,83.25 214.97,83.32 215.31,83.54 215.52,83.86 215.6,84.25 215.6,117.1 215.53,117.47 215.31,117.81 214.99,118.02 214.6,118.1 207.75,118.1 207.64,118.14 207.6,118.25 207.6,127.25 207.64,127.36 207.75,127.4 220.6,127.4 221.47,127.32 222.31,127.1 223.1,126.73 223.81,126.23 224.43,125.61 224.93,124.9 225.3,124.11 225.52,123.27 225.6,122.4 225.6,106 225.67,105.63 225.89,105.29 226.21,105.08 226.6,105 231.5,105 231.89,104.92 232.21,104.71 232.43,104.37 232.5,104 232.5,89 232.42,88.61 232.21,88.29 231.87,88.07 231.5,88 226.6,88 226.23,87.93 225.89,87.71 225.68,87.39 225.6,87 225.6,78.9 225.52,78.03 225.3,77.19 224.93,76.4 224.43,75.69 223.81,75.07 223.1,74.57 222.31,74.2 221.47,73.98 220.6,73.9
HVW_3_4 on TOP: 208,64.3 207.88,64.33 207.78,64.42 207.75,64.55 207.75,69.05 207.72,69.17 207.62,69.27 207.5,69.3 206.9,69.3 206.78,69.33 206.68,69.42 206.65,69.55 206.65,72.25 206.68,72.38 206.78,72.47 206.9,72.5 214.35,72.5 214.47,72.47 214.57,72.38 214.6,72.25 214.6,64.55 214.57,64.42 214.47,64.33 214.35,64.3
HVW_3_4 on TOP: 207.8,107.4 207.68,107.43 207.58,107.53 207.55,107.65 207.55,108.35 207.48,108.53 207.3,108.6 203.15,108.6 203.04,108.64 203,108.75 203,115.25 203.04,115.36 203.15,115.4 207.3,115.4 207.48,115.47 207.55,115.65 207.55,116.35 207.58,116.47 207.68,116.57 207.8,116.6 213.05,116.6 213.18,116.57 213.27,116.47 213.3,116.35 213.3,107.65 213.27,107.53 213.18,107.43 213.05,107.4
HVW_3_4 on BOTTOM: 208.05,64.3 207.93,64.33 207.83,64.42 207.8,64.55 207.8,72.1 207.83,72.22 207.93,72.32 208.05,72.35 214.35,72.35 214.47,72.32 214.57,72.22 214.6,72.1 214.6,64.55 214.57,64.42 214.47,64.33 214.35,64.3
HVW_3_4 on BOTTOM: 207.95,107.4 207.82,107.43 207.73,107.53 207.7,107.65 207.7,116.35 207.73,116.47 207.82,116.57 207.95,116.6 213.05,116.6 213.18,116.57 213.27,116.47 213.3,116.35 213.3,107.65 213.27,107.53 213.18,107.43 213.05,107.4
HVW_3_4 on CONDUCTIVE4: 207.75,63.2 207.64,63.24 207.6,63.35 207.6,72.35 207.64,72.46 207.75,72.5 215.25,72.5 215.62,72.57 215.96,72.79 216.17,73.11 216.25,73.5 216.25,106.35 216.18,106.72 215.96,107.06 215.64,107.27 215.25,107.35 207.75,107.35 207.64,107.39 207.6,107.5 207.6,116.5 207.64,116.61 207.75,116.65 221.25,116.65 222.12,116.57 222.96,116.35 223.75,115.98 224.46,115.48 225.08,114.86 225.58,114.15 225.95,113.36 226.17,112.52 226.25,111.65 226.25,89 226.32,88.63 226.54,88.29 226.86,88.08 227.25,88 231.5,88 231.89,87.92 232.21,87.71 232.43,87.37 232.5,87 232.5,67.25 232.42,66.86 232.21,66.54 231.87,66.32 231.5,66.25 226.35,66.25 226.31,66.26 223.54,63.49 223.21,63.27 222.84,63.2
LDO_15VOUT on BOTTOM (solid shape): 165.41,36.57 165.95,36.77 167.07,36.48 167.45,36 167.07,35.52 165.95,35.23 165.89,35.21 165.82,35.21 165.38,35.48 165.42,36
LDO_15VOUT on TOP: 161.75,35.15 161.62,35.18 161.53,35.27 161.5,35.4 161.5,35.89 161.51,35.95 161.54,35.99 161.83,36.28 161.88,36.32 162,36.35 164.5,36.35 164.62,36.38 164.67,36.42 165.18,36.93 165.23,36.97 165.35,37 166.15,37 166.21,36.99 166.32,36.93 166.68,36.57 166.72,36.52 166.75,36.4 166.75,35.75 166.74,35.69 166.68,35.58 166.32,35.22 166.27,35.18 166.15,35.15
LDO_15VOUT on BOTTOM: 165.35,33.75 165.29,33.76 165.18,33.82 164.79,34.21 164.76,34.25 164.75,34.31 164.75,36.15 164.76,36.21 164.82,36.32 165.26,36.76 165.3,36.79 165.36,36.8 166.29,36.8 166.35,36.79 166.39,36.76 166.68,36.47 166.72,36.42 166.75,36.3 166.75,34 166.72,33.88 166.62,33.78 166.5,33.75
LT8316_SENSE_B on TOP: 54.6,21.35 54.49,21.39 54.45,21.5 54.45,22.65 53.54,23.56 53.51,23.6 53.5,23.66 53.5,27.65 53.53,27.77 53.62,27.87 53.75,27.9 58.35,27.9 58.48,27.87 58.57,27.77 58.6,27.65 58.6,21.91 58.59,21.85 58.56,21.81 58.14,21.39 58.1,21.36 58.04,21.35
OUT_U on TOP: 30.85,98.75 30.73,98.78 30.63,98.88 30.6,99 30.6,105.9 30.63,106.03 30.73,106.12 30.85,106.15 42.55,106.15 42.67,106.12 42.77,106.03 42.8,105.9 42.8,99 42.77,98.88 42.67,98.78 42.55,98.75
OUT_U on BOTTOM: 30.85,98.7 30.73,98.73 30.63,98.83 30.6,98.95 30.6,105.9 30.63,106.03 30.73,106.12 30.85,106.15 38.35,106.15 38.48,106.12 38.57,106.03 38.6,105.9 38.6,98.95 38.57,98.83 38.48,98.73 38.35,98.7
OUT_U on CONDUCTIVE5: 135.53,5 135.47,5.01 135.36,5.07 119.96,20.46 103.22,37.21 102.91,37.42 102.51,37.5 60.9,37.5 58.99,37.88 57.36,38.96 49.56,46.76 48.48,48.39 48.1,50.3 48.1,53.73 41.46,60.36 40.38,61.99 40,63.9 40,97.85 39.97,97.97 39.93,98.02 39.27,98.68 39.16,98.74 39.1,98.75 30.8,98.75 30.68,98.78 30.58,98.88 30.55,99 30.55,105.75 30.58,105.88 30.68,105.97 30.8,106 38.95,106 39.07,106.03 39.12,106.07 39.66,106.61 39.7,106.64 39.76,106.65 45,106.65 45.87,106.57 46.71,106.35 47.5,105.98 48.21,105.48 48.83,104.86 49.33,104.15 49.7,103.36 49.92,102.52 50,101.65 50,65.97 56.64,59.34 57.72,57.71 58.1,55.8 58.1,52.37 62.97,47.5 105,47.5 105.44,47.48 106.29,47.33 107.11,47.03 107.87,46.6 108.54,46.04 138.58,15.99 138.62,15.94 138.65,15.82 138.65,5.85 138.64,5.79 138.58,5.68 137.97,5.07 137.92,5.03 137.8,5
OUT_V on TOP: 118.1,69.75 117.97,69.78 117.88,69.88 117.85,70 117.85,79.3 117.88,79.42 117.97,79.52 118.1,79.55 125,79.55 125.12,79.52 125.22,79.42 125.25,79.3 125.25,70 125.22,69.88 125.12,69.78 125,69.75
OUT_V on BOTTOM: 118.1,69.75 117.97,69.78 117.88,69.88 117.85,70 117.85,77.6 117.88,77.72 117.97,77.82 118.1,77.85 125,77.85 125.12,77.82 125.22,77.72 125.25,77.6 125.25,70 125.22,69.88 125.12,69.78 125,69.75
OUT_V on CONDUCTIVE5: 143.5,18.14 118.46,43.18 117.38,44.8 117,46.71 117,67.43 117.01,67.5 117.09,67.64 117.76,68.31 117.84,68.45 117.85,68.52 117.85,77.85 117.89,77.96 118,78 124.95,78 125.1,77.96 125.21,77.85 125.25,77.7 125.25,68.62 125.29,68.47 125.34,68.41 126.93,66.82 126.97,66.77 127,66.65 127,48.78 152.04,23.75 153.12,22.13 153.5,20.21 153.5,10 148.5,5 143.5,10
OUT_W on TOP: 203.05,97 202.93,97.03 202.83,97.12 202.8,97.25 202.8,104.15 202.83,104.28 202.93,104.37 203.05,104.4 213.25,104.4 213.38,104.37 213.47,104.28 213.5,104.15 213.5,97.25 213.47,97.12 213.38,97.03 213.25,97
OUT_W on BOTTOM: 205.6,97 205.47,97.03 205.38,97.12 205.35,97.25 205.35,104.15 205.38,104.28 205.47,104.37 205.6,104.4 213.15,104.4 213.28,104.37 213.37,104.28 213.4,104.15 213.4,97.25 213.37,97.12 213.28,97.03 213.15,97
OUT_W on CONDUCTIVE5: 159.2,5 159.14,5.01 159.03,5.07 158.42,5.68 158.38,5.73 158.35,5.85 158.35,14.15 158.36,14.21 158.42,14.32 159.03,14.93 159.08,14.97 159.2,15 160.6,15 160.6,18.39 160.98,20.3 162.06,21.92 171.5,31.36 171.5,45.5 171.88,47.41 172.96,49.04 180.44,56.51 182.06,57.59 183.97,57.97 186.4,57.97 193.5,65.07 193.5,99.55 193.58,100.42 193.8,101.26 194.17,102.05 194.67,102.76 195.29,103.38 196,103.88 196.79,104.25 197.63,104.47 198.5,104.55 213.35,104.55 213.46,104.51 213.5,104.4 213.5,96.9 213.46,96.79 213.35,96.75 204.5,96.75 204.13,96.68 203.79,96.46 203.58,96.14 203.5,95.75 203.5,63 203.12,61.09 202.04,59.46 192.01,49.44 190.39,48.35 188.47,47.97 186.04,47.97 181.5,43.43 181.5,29.29 181.12,27.37 180.04,25.75 170.6,16.32 170.6,7.62 170.59,7.55 170.51,7.41 168.19,5.09 168.13,5.04 167.98,5
PC_G_U1 on TOP (solid shape): 48.77,130.43 49.19,130.43 49.19,131.47 50.04,131.47 50.04,130.43 50.46,130.43 50.46,131.47 51.31,131.47 51.31,130.43 51.73,130.43 51.73,131.47 52.58,131.47 52.58,127.95 53.01,127.95 53.01,127.55 52.58,127.55 52.58,126.67 47.92,126.67 47.92,127.55 47.49,127.55 47.49,127.95 47.92,127.95 47.92,131.47 48.77,131.47
PC_G_U1 on TOP (solid shape): 59.06,135.28 59.23,134.98 59.64,134.58 59.41,134.06 58.41,133.47 57.8,133.55 57.72,134.16 58.31,135.16 58.49,135.34 58.74,135.4
PC_G_U1 on TOP: 48.2,126.7 48.14,126.71 48.03,126.77 44.59,130.21 44.56,130.25 44.55,130.31 44.55,130.6 44.48,130.78 44.3,130.85 40.15,130.85 40.04,130.89 40,131 40,137.5 40.04,137.61 40.15,137.65 44.7,137.65 44.76,137.64 44.87,137.58 47.43,135.02 47.54,134.96 47.6,134.95 51.05,134.95 51.17,134.92 51.27,134.82 51.3,134.7 51.3,133.78 51.33,133.65 51.42,133.56 51.55,133.53 52.25,133.53 52.36,133.48 52.4,133.38 52.4,126.95 52.37,126.83 52.27,126.73 52.15,126.7
PC_G_U2 on TOP (solid shape): 48.77,121.17 49.19,121.17 49.19,122.22 50.04,122.22 50.04,121.17 50.46,121.17 50.46,122.22 51.31,122.22 51.31,121.17 51.73,121.17 51.73,122.22 52.58,122.22 52.58,118.7 53.01,118.7 53.01,118.3 52.58,118.3 52.58,117.42 47.92,117.42 47.92,118.3 47.49,118.3 47.49,118.7 47.92,118.7 47.92,122.22 48.77,122.22
PC_G_U2 on TOP (solid shape): 59.06,126.03 59.23,125.73 59.64,125.33 59.41,124.81 58.41,124.22 57.8,124.3 57.72,124.91 58.31,125.91 58.49,126.09 58.74,126.15
PC_G_U2 on TOP: 48.2,117.45 48.14,117.46 48.03,117.52 48,117.55 45.75,117.55 45.69,117.56 45.58,117.62 44.62,118.58 44.58,118.63 44.55,118.75 44.55,119.85 44.48,120.03 44.3,120.1 40.15,120.1 40.04,120.14 40,120.25 40,126.75 40.04,126.86 40.15,126.9 45.3,126.9 45.36,126.89 45.47,126.83 46.53,125.77 46.64,125.71 46.7,125.7 51.05,125.7 51.17,125.67 51.27,125.58 51.3,125.45 51.3,124.5 51.33,124.38 51.42,124.28 51.55,124.25 52.15,124.25 52.27,124.22 52.37,124.12 52.4,124 52.4,117.7 52.37,117.58 52.27,117.48 52.15,117.45
PC_G_U3 on TOP (solid shape): 48.77,111.92 49.19,111.92 49.19,112.97 50.04,112.97 50.04,111.92 50.46,111.92 50.46,112.97 51.31,112.97 51.31,111.92 51.73,111.92 51.73,112.97 52.58,112.97 52.58,109.45 53.01,109.45 53.01,109.05 52.58,109.05 52.58,108.17 47.92,108.17 47.92,109.05 47.49,109.05 47.49,109.45 47.92,109.45 47.92,112.97 48.77,112.97
PC_G_U3 on TOP (solid shape): 59.06,116.78 59.23,116.48 59.64,116.08 59.41,115.56 58.41,114.97 57.8,115.05 57.72,115.66 58.31,116.66 58.49,116.84 58.74,116.9
PC_G_U3 on TOP: 48.35,108.2 48.23,108.23 48.13,108.33 48.1,108.45 48.1,109.1 48.07,109.22 47.98,109.32 47.85,109.35 40.15,109.35 40.04,109.39 40,109.5 40,116 40.04,116.11 40.15,116.15 47.9,116.15 48.05,116.2 48.2,116.42 48.29,116.45 51.05,116.45 51.17,116.42 51.27,116.33 51.3,116.2 51.3,115.25 51.33,115.12 51.42,115.03 51.55,115 52.15,115 52.27,114.97 52.37,114.88 52.4,114.75 52.4,108.45 52.37,108.33 52.27,108.23 52.15,108.2
PC_G_U5 on TOP (solid shape): 48.77,89.83 49.19,89.83 49.19,90.88 50.04,90.88 50.04,89.83 50.46,89.83 50.46,90.88 51.31,90.88 51.31,89.83 51.73,89.83 51.73,90.88 52.58,90.88 52.58,87.35 53.01,87.35 53.01,86.95 52.58,86.95 52.58,86.08 47.92,86.08 47.92,86.95 47.49,86.95 47.49,87.35 47.92,87.35 47.92,90.88 48.77,90.88
PC_G_U5 on TOP (solid shape): 59.06,94.68 59.23,94.38 59.64,93.98 59.41,93.46 58.41,92.87 57.8,92.95 57.72,93.56 58.31,94.56 58.49,94.74 58.74,94.8
PC_G_U5 on TOP: 45,86.1 44.88,86.13 44.78,86.22 44.75,86.35 44.75,90.7 44.66,90.91 44.45,91 43.8,91 43.69,91.04 43.65,91.15 43.65,94.5 43.68,94.62 43.77,94.72 43.9,94.75 47.05,94.75 47.11,94.74 47.22,94.68 47.48,94.42 47.59,94.36 47.65,94.35 51.05,94.35 51.17,94.32 51.27,94.22 51.3,94.1 51.3,93.15 51.33,93.03 51.42,92.93 51.55,92.9 52.15,92.9 52.27,92.87 52.37,92.78 52.4,92.65 52.4,86.35 52.37,86.22 52.27,86.13 52.15,86.1
PC_G_U6 on TOP (solid shape): 48.77,80.58 49.19,80.58 49.19,81.62 50.04,81.62 50.04,80.58 50.46,80.58 50.46,81.62 51.31,81.62 51.31,80.58 51.73,80.58 51.73,81.62 52.58,81.62 52.58,78.1 53.01,78.1 53.01,77.7 52.58,77.7 52.58,76.83 47.92,76.83 47.92,77.7 47.49,77.7 47.49,78.1 47.92,78.1 47.92,81.62 48.77,81.62
PC_G_U6 on TOP (solid shape): 59.06,85.43 59.23,85.13 59.64,84.73 59.41,84.21 58.41,83.62 57.8,83.7 57.72,84.31 58.31,85.31 58.49,85.49 58.74,85.55
PC_G_U6 on TOP: 45,76.85 44.88,76.88 44.78,76.97 44.75,77.1 44.75,79.95 44.66,80.16 44.45,80.25 43.8,80.25 43.69,80.29 43.65,80.4 43.65,84.85 43.68,84.97 43.77,85.07 43.9,85.1 51.05,85.1 51.17,85.07 51.27,84.97 51.3,84.85 51.3,83.92 51.33,83.8 51.42,83.71 51.55,83.67 52.25,83.67 52.36,83.63 52.4,83.53 52.4,77.1 52.37,76.97 52.27,76.88 52.15,76.85
PC_G_U7 on TOP (solid shape): 48.77,71.33 49.19,71.33 49.19,72.38 50.04,72.38 50.04,71.33 50.46,71.33 50.46,72.38 51.31,72.38 51.31,71.33 51.73,71.33 51.73,72.38 52.58,72.38 52.58,68.85 53.01,68.85 53.01,68.45 52.58,68.45 52.58,67.58 47.92,67.58 47.92,68.45 47.49,68.45 47.49,68.85 47.92,68.85 47.92,72.38 48.77,72.38
PC_G_U7 on TOP: 45,67.6 44.88,67.63 44.78,67.72 44.75,67.85 44.75,69.2 44.66,69.41 44.45,69.5 43.8,69.5 43.69,69.54 43.65,69.65 43.65,73.1 43.69,73.21 43.8,73.25 44.8,73.25 44.92,73.28 44.97,73.32 47.43,75.78 47.48,75.82 47.6,75.85 51.05,75.85 51.17,75.82 51.27,75.72 51.3,75.6 51.3,74.65 51.33,74.53 51.42,74.43 51.55,74.4 52.15,74.4 52.27,74.37 52.37,74.28 52.4,74.15 52.4,67.85 52.37,67.72 52.27,67.63 52.15,67.6
PC_G_U8 on TOP: 48.35,61.5 48.23,61.53 48.13,61.62 48.1,61.75 48.1,66.35 48.13,66.47 48.23,66.57 48.35,66.6 51.05,66.6 51.17,66.57 51.27,66.47 51.3,66.35 51.3,65.35 51.33,65.22 51.42,65.13 51.55,65.1 59.3,65.1 59.42,65.07 59.52,64.97 59.55,64.85 59.55,61.65 59.51,61.54 59.4,61.5
PC_G_V1 on TOP (solid shape): 96.45,91.83 97.33,91.83 97.33,87.17 96.45,87.17 96.45,86.75 96.05,86.75 96.05,87.17 92.53,87.17 92.53,88.02 93.58,88.02 93.58,88.44 92.53,88.44 92.53,89.29 93.58,89.29 93.58,89.71 92.53,89.71 92.53,90.56 93.58,90.56 93.58,90.98 92.53,90.98 92.53,91.83 96.05,91.83 96.05,92.25 96.45,92.25
PC_G_V1 on TOP (solid shape): 89.42,98.89 89.94,98.66 90.58,97.53 90.6,97.4 90.45,97.05 90.1,96.9 89.97,96.92 89.84,96.97 88.84,97.56 88.61,98.08 89.02,98.48
PC_G_V1 on TOP: 86.5,79.25 86.39,79.29 86.35,79.4 86.35,83.95 86.36,84.01 86.42,84.12 88.98,86.68 89.04,86.79 89.05,86.85 89.05,90.3 89.08,90.42 89.17,90.52 89.3,90.55 90.22,90.55 90.35,90.58 90.44,90.67 90.47,90.8 90.47,91.5 90.52,91.61 90.62,91.65 97.05,91.65 97.17,91.62 97.27,91.53 97.3,91.4 97.3,87.45 97.29,87.39 97.23,87.28 93.79,83.84 93.75,83.81 93.69,83.8 93.4,83.8 93.22,83.73 93.15,83.55 93.15,79.4 93.11,79.29 93,79.25
PC_G_V2 on TOP (solid shape): 105.7,91.83 106.58,91.83 106.58,87.17 105.7,87.17 105.7,86.75 105.3,86.75 105.3,87.17 101.78,87.17 101.78,88.02 102.83,88.02 102.83,88.44 101.78,88.44 101.78,89.29 102.83,89.29 102.83,89.71 101.78,89.71 101.78,90.56 102.83,90.56 102.83,90.98 101.78,90.98 101.78,91.83 105.3,91.83 105.3,92.25 105.7,92.25
PC_G_V2 on TOP (solid shape): 98.67,98.89 99.19,98.66 99.83,97.53 99.85,97.4 99.7,97.05 99.35,96.9 99.22,96.92 99.09,96.97 98.09,97.56 97.86,98.08 98.27,98.48
PC_G_V2 on TOP: 97.25,79.25 97.14,79.29 97.1,79.4 97.1,84.55 97.11,84.61 97.17,84.72 98.23,85.78 98.29,85.89 98.3,85.95 98.3,90.3 98.33,90.42 98.42,90.52 98.55,90.55 99.47,90.55 99.6,90.58 99.69,90.67 99.72,90.8 99.72,91.5 99.77,91.61 99.88,91.65 106.3,91.65 106.42,91.62 106.52,91.53 106.55,91.4 106.55,87.45 106.54,87.39 106.48,87.28 106.45,87.25 106.45,85 106.44,84.94 106.38,84.83 105.42,83.87 105.37,83.83 105.25,83.8 104.15,83.8 103.97,83.73 103.9,83.55 103.9,79.4 103.86,79.29 103.75,79.25
PC_G_V3 on TOP (solid shape): 114.95,91.83 115.83,91.83 115.83,87.17 114.95,87.17 114.95,86.75 114.55,86.75 114.55,87.17 111.03,87.17 111.03,88.02 112.08,88.02 112.08,88.44 111.03,88.44 111.03,89.29 112.08,89.29 112.08,89.71 111.03,89.71 111.03,90.56 112.08,90.56 112.08,90.98 111.03,90.98 111.03,91.83 114.55,91.83 114.55,92.25 114.95,92.25
PC_G_V3 on TOP (solid shape): 107.92,98.89 108.44,98.66 109.08,97.53 109.1,97.4 108.95,97.05 108.6,96.9 108.47,96.92 108.34,96.97 107.34,97.56 107.11,98.08 107.52,98.48
PC_G_V3 on TOP: 108,79.25 107.89,79.29 107.85,79.4 107.85,87.15 107.8,87.3 107.58,87.45 107.55,87.54 107.55,90.3 107.58,90.42 107.67,90.52 107.8,90.55 108.72,90.55 108.85,90.58 108.94,90.67 108.97,90.8 108.97,91.5 109.02,91.61 109.12,91.65 115.55,91.65 115.67,91.62 115.77,91.53 115.8,91.4 115.8,87.6 115.77,87.47 115.67,87.38 115.55,87.35 114.9,87.35 114.78,87.32 114.68,87.22 114.65,87.1 114.65,79.4 114.61,79.29 114.5,79.25
PC_G_V5 on TOP (solid shape): 137.05,91.83 137.93,91.83 137.93,87.17 137.05,87.17 137.05,86.75 136.65,86.75 136.65,87.17 133.12,87.17 133.12,88.02 134.18,88.02 134.18,88.44 133.12,88.44 133.12,89.29 134.18,89.29 134.18,89.71 133.12,89.71 133.12,90.56 134.18,90.56 134.18,90.98 133.12,90.98 133.12,91.83 136.65,91.83 136.65,92.25 137.05,92.25
PC_G_V5 on TOP (solid shape): 130.02,98.89 130.54,98.66 131.18,97.53 131.2,97.4 131.05,97.05 130.7,96.9 130.57,96.92 130.44,96.97 129.44,97.56 129.21,98.08 129.62,98.48
PC_G_V5 on TOP: 129.5,82.9 129.38,82.93 129.28,83.03 129.25,83.15 129.25,86.3 129.26,86.36 129.32,86.47 129.58,86.73 129.64,86.84 129.65,86.9 129.65,90.3 129.68,90.42 129.78,90.52 129.9,90.55 130.82,90.55 130.95,90.58 131.04,90.67 131.07,90.8 131.07,91.5 131.12,91.61 131.22,91.65 137.65,91.65 137.78,91.62 137.87,91.53 137.9,91.4 137.9,84.25 137.87,84.12 137.78,84.03 137.65,84 133.3,84 133.09,83.91 133,83.7 133,83.05 132.96,82.94 132.85,82.9
PC_G_V6 on TOP (solid shape): 146.3,91.83 147.18,91.83 147.18,87.17 146.3,87.17 146.3,86.75 145.9,86.75 145.9,87.17 142.38,87.17 142.38,88.02 143.43,88.02 143.43,88.44 142.38,88.44 142.38,89.29 143.43,89.29 143.43,89.71 142.38,89.71 142.38,90.56 143.43,90.56 143.43,90.98 142.38,90.98 142.38,91.83 145.9,91.83 145.9,92.25 146.3,92.25
PC_G_V6 on TOP (solid shape): 139.27,98.89 139.79,98.66 140.43,97.53 140.45,97.4 140.3,97.05 139.95,96.9 139.82,96.92 139.69,96.97 138.69,97.56 138.46,98.08 138.87,98.48
PC_G_V6 on TOP: 139.15,82.9 139.03,82.93 138.93,83.03 138.9,83.15 138.9,90.3 138.93,90.42 139.03,90.52 139.15,90.55 140.07,90.55 140.2,90.58 140.29,90.67 140.32,90.8 140.32,91.5 140.37,91.61 140.47,91.65 146.9,91.65 147.03,91.62 147.12,91.53 147.15,91.4 147.15,84.25 147.12,84.12 147.03,84.03 146.9,84 144.05,84 143.84,83.91 143.75,83.7 143.75,83.05 143.71,82.94 143.6,82.9
PC_G_V7 on TOP (solid shape): 155.55,91.83 156.43,91.83 156.43,87.17 155.55,87.17 155.55,86.75 155.15,86.75 155.15,87.17 151.62,87.17 151.62,88.02 152.68,88.02 152.68,88.44 151.62,88.44 151.62,89.29 152.68,89.29 152.68,89.71 151.62,89.71 151.62,90.56 152.68,90.56 152.68,90.98 151.62,90.98 151.62,91.83 155.15,91.83 155.15,92.25 155.55,92.25
PC_G_V7 on TOP: 150.9,82.9 150.79,82.94 150.75,83.05 150.75,84.05 150.72,84.17 150.68,84.22 148.22,86.68 148.18,86.73 148.15,86.85 148.15,90.3 148.18,90.42 148.28,90.52 148.4,90.55 149.32,90.55 149.45,90.58 149.54,90.67 149.57,90.8 149.57,91.5 149.62,91.61 149.72,91.65 156.15,91.65 156.28,91.62 156.37,91.53 156.4,91.4 156.4,84.25 156.37,84.12 156.28,84.03 156.15,84 154.8,84 154.59,83.91 154.5,83.7 154.5,83.05 154.46,82.94 154.35,82.9
